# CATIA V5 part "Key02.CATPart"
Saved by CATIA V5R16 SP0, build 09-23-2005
Part number: Key02
Bounding box of the stored display mesh (mm): x -3.481 to 16.481, y -3.5 to 3.5, z 0 to 8
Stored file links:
  C:\V5_education\CATIA Data\ASD\Power Transmission Gear Assembly\Assembly Data\Key02.CATPart
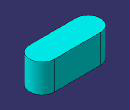
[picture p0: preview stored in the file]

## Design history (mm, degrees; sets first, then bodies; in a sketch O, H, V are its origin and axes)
Set1 "Reference Data"
  Point1 "Center Point": (0, 0, 0)
Body1 (main body)
  Sketch1 on xy-plane, origin (0, 0, 0), H (1, 0, 0), V (0, 1, 0)
    construction line L1 (0, 0) -> (13, 0)
    line L2 (0, 3.5) -> (13, 3.5)
    line L3 (13, -3.5) -> (0, -3.5)
    arc A1 centre (13, 0) radius 3.5 from (13, 3.5) to (13, -3.5) cw
    arc A2 centre (0, 0) radius 3.5 from (0, -3.5) to (0, 3.5) cw
    distance L1 L2 = 3.5
    distance A2 A1 = 20
    horizontal: L1 H
    tangency: A1 L2, A2 L2, A1 L3, A2 L3
  Pad1: profile Sketch1, direction (0, 0, 1), length 8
